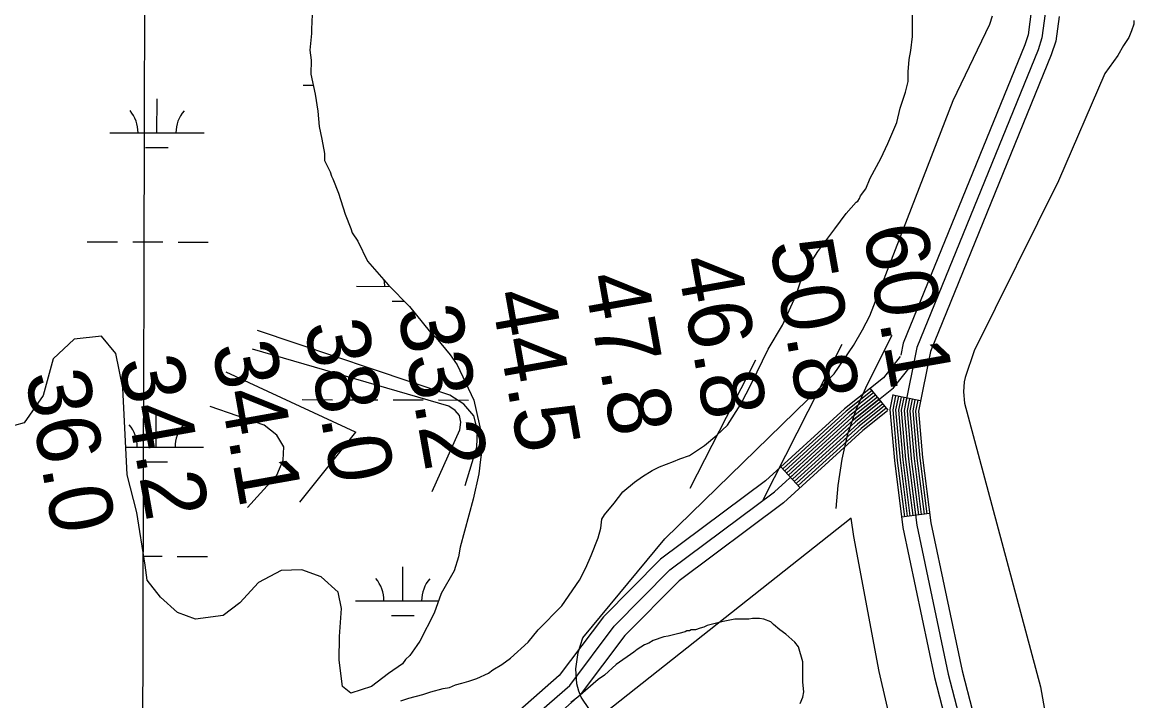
# Model space of a CAD drawing. Extents: x 3161665 to 3199565, y 885729 to 911164.
# Drawn here: x 3181436 to 3182612, y 894901 to 895619 of the extents above; entities that cross this region are included whole.
import ezdxf

# ---------------------------------------------------------------- set-up
doc = ezdxf.new("R2010")
doc.units = 0
for name, color, linetype in [('V-GRID-MAJR', 7, 'Continuous'), ('V-LEVE-TOET', 7, 'Continuous'), ('V-RIVR-RANG', 7, 'Continuous'), ('V-ROAD-CNTR', 7, 'Continuous'), ('V-SITE-VEGE', 7, 'Continuous'), ('V-TOPO-MAJR', 7, 'Continuous'), ('V-TOPO-MINR', 7, 'Continuous'), ('V-WETL-SWMP', 7, 'Continuous')]:
    doc.layers.add(name, color=color, linetype=linetype)

msp = doc.modelspace()

# ---------------------------------------------------------------- linework, layer by layer
at = {"layer": 'V-GRID-MAJR'}
msp.add_spline([(3181553.2, 891152.2), (3181570, 897211.5), (3181586.7, 903274.3), (3181603.5, 909337.1), (3181603.5, 909340.5)], degree=3, dxfattribs=at)
at = {"layer": 'V-LEVE-TOET'}
for points in [[(3182036.4, 894891.6), (3182027.8, 894904.4), (3182025, 894911), (3182023, 894918.6), (3182022.1, 894934.6), (3182024.5, 894951.6), (3182029.4, 894967.4), (3182116.1, 895071.9), (3182295.5, 895246.7), (3182315.8, 895276.7), (3182325.3, 895293.3), (3182333.3, 895308), (3182421.3, 895535.9), (3182460.1, 895616.9), (3182462.8, 895625.4)], [(3182612.4, 895620.5), (3182612.4, 895616.7), (3182610.1, 895609.5), (3182607.1, 895602.7), (3182601.6, 895594.3), (3182595.6, 895583.6), (3182581.8, 895564.4), (3182532.7, 895451.1), (3182443.5, 895271.1), (3182433.9, 895242.9), (3182433.1, 895238.3), (3182432.2, 895227.5), (3182433.2, 895215.6), (3182513.7, 894915.5), (3182565.9, 894618.7)], [(3182392.9, 894716.8), (3182343.1, 894931.5), (3182316.2, 895074.4), (3182313.5, 895094), (3182053.3, 894888.4)]]:
    msp.add_lwpolyline(points, dxfattribs=at)
at = {"layer": 'V-ROAD-CNTR'}
for p, q in [((3182352.4, 895208.1), (3182333.6, 895231.5)), ((3182386.8, 895218.1), (3182357.4, 895224.1)), ((3182259.3, 895126.2), (3182239.1, 895148.4)), ((3182396.4, 895098.9), (3182366.7, 895095.1))]:
    msp.add_line(p, q, dxfattribs=at)
for points in [[(3182186, 897012.1), (3182128.5, 896707.1), (3182101.9, 896553.8), (3182092.4, 896498.4), (3182091.5, 896433.3), (3182116.3, 896348.5), (3182137.8, 896319.4), (3182301.4, 896052), (3182392.7, 895899.5), (3182447.6, 895808.6), (3182483.2, 895746), (3182489.6, 895725.4), (3182502.9, 895675.6), (3182505.8, 895644.3), (3182500.6, 895605.6), (3182497, 895594.9), (3182368.5, 895279), (3182366.1, 895266.6)], [(3182520.9, 895644), (3182515.3, 895602.1), (3182511.1, 895589.7), (3182383, 895274.7), (3182369.4, 895208), (3182374, 895156.4), (3182382.9, 895086.5), (3182416.2, 894928.7), (3182470.9, 894717.4)], [(3182533.4, 895624.9), (3182530, 895598.7), (3182525.1, 895584.4), (3182397.4, 895270.3), (3182384.6, 895207.1), (3182388.9, 895158), (3182397.7, 895089), (3182430.8, 894932.2), (3182485.5, 894720.8)], [(3182365.4, 895265.2), (3182347.5, 895242.6), (3182306.2, 895209.5), (3182222.7, 895133.4), (3182111.7, 895050.4), (3182051.1, 894989.5), (3182004.4, 894927.3), (3181947.9, 894877.6), (3181907, 894855.9), (3181840.5, 894847.8), (3181780.8, 894854.2), (3181703.8, 894842.1), (3181580.2, 894803.2), (3181488.8, 894772.4), (3181360.2, 894715.8), (3181245.5, 894652.3), (3181099.7, 894575.8), (3180964.1, 894510.3)], [(3181366.8, 894702.4), (3181494.3, 894758.4), (3181584.8, 894788.9), (3181707.2, 894827.4), (3181781.2, 894839), (3181840.6, 894832.7), (3181911.6, 894841.4), (3181956.5, 894865.2), (3182015.5, 894917), (3182062.5, 894979.6), (3182121.6, 895039.1), (3182232.2, 895121.9), (3182316, 895198.1), (3182358.2, 895232), (3182377.2, 895255.9)], [(3182335.5, 895229.1), (3182308.2, 895207.2), (3182241.1, 895146.2)], [(3182357.5, 895224.7), (3182354.3, 895208.8), (3182359.1, 895154.8), (3182368.1, 895084), (3182401.6, 894925.3), (3182456.3, 894713.9), (3182481.4, 894597.4), (3182490.3, 894538.3), (3182490.2, 894502.8), (3182466.9, 894475.2), (3182452.5, 894467.5), (3182405, 894454.4), (3182202.3, 894432.3), (3182163.1, 894419), (3182124.8, 894399.2), (3182097, 894380.7), (3182070.1, 894351.7), (3182049.1, 894300.2), (3182042.8, 894254), (3182048.3, 894102.2), (3182076, 893799.8), (3182076.4, 893721.6)], [(3182337.4, 895226.8), (3182310.1, 895204.9), (3182243.1, 895143.9)], [(3182339.3, 895224.4), (3182312.1, 895202.6), (3182245.1, 895141.7)], [(3182341.1, 895222.1), (3182314, 895200.4), (3182247.1, 895139.5)], [(3182343, 895219.8), (3182316, 895198.1), (3182249.2, 895137.3)], [(3182344.9, 895217.4), (3182317.9, 895195.8), (3182251.2, 895135.1)], [(3182360.3, 895223.5), (3182357.3, 895208.7), (3182362.1, 895155.1), (3182369.7, 895095.5)], [(3182363.3, 895222.9), (3182360.4, 895208.5), (3182365.1, 895155.4), (3182372.6, 895095.9)], [(3182366.2, 895222.3), (3182363.4, 895208.3), (3182368, 895155.7), (3182375.6, 895096.3)], [(3182369.2, 895221.7), (3182366.4, 895208.2), (3182371, 895156), (3182378.6, 895096.6)], [(3182372.1, 895221.1), (3182369.4, 895208), (3182374, 895156.4), (3182381.6, 895097)], [(3182375, 895220.5), (3182372.5, 895207.8), (3182377, 895156.7), (3182384.5, 895097.4)], [(3182378, 895219.9), (3182375.5, 895207.6), (3182380, 895157), (3182387.5, 895097.8)], [(3182380.9, 895219.3), (3182378.5, 895207.5), (3182383, 895157.3), (3182390.5, 895098.2)], [(3182383.9, 895218.7), (3182381.5, 895207.3), (3182385.9, 895157.6), (3182393.5, 895098.5)], [(3182351.7, 895207.5), (3182325.7, 895186.7), (3182241.8, 895110.3), (3182131.5, 895027.7), (3182073.8, 894969.8), (3182026.6, 894906.8), (3181965.1, 894852.8), (3181916.2, 894826.8), (3181840.7, 894817.6), (3181781.6, 894823.9), (3181710.6, 894812.8), (3181589.5, 894774.7), (3181499.7, 894744.4), (3181373.5, 894688.9)], [(3182346.8, 895215.1), (3182319.9, 895193.5), (3182253.2, 895132.8)], [(3182348.7, 895212.8), (3182321.8, 895191.2), (3182255.2, 895130.6)], [(3182350.5, 895210.4), (3182323.8, 895189), (3182257.2, 895128.4)]]:
    msp.add_lwpolyline(points, dxfattribs=at)
at = {"layer": 'V-SITE-VEGE'}
for p, q in [((3182378.4, 895603.8), (3182378.4, 895634.7)), ((3182376.6, 895588.8), (3182378.4, 895603.8)), ((3182374.7, 895579.4), (3182376.6, 895588.8)), ((3182373.8, 895566.3), (3182374.7, 895579.4)), ((3182373.8, 895556), (3182373.8, 895566.3)), ((3182370.9, 895544.7), (3182373.8, 895556)), ((3182365.3, 895527.8), (3182370.9, 895544.7)), ((3182361.6, 895512.8), (3182365.3, 895527.8)), ((3182352.2, 895490.3), (3182361.6, 895512.8)), ((3182344.7, 895474.4), (3182352.2, 895490.3)), ((3182333.5, 895453.8), (3182344.7, 895474.4)), ((3182328.8, 895442.5), (3182333.5, 895453.8)), ((3182323.1, 895435), (3182328.8, 895442.5)), ((3182318.5, 895428.5), (3182320.3, 895429.4)), ((3182320.3, 895429.4), (3182322.2, 895432.2)), ((3182322.2, 895432.2), (3182323.1, 895435)), ((3182308.1, 895416.3), (3182318.5, 895428.5)), ((3182296, 895400.3), (3182308.1, 895416.3)), ((3182278.2, 895376), (3182296, 895400.3)), ((3182269.7, 895362.8), (3182278.2, 895376)), ((3182260.3, 895346), (3182269.7, 895362.8)), ((3182254.7, 895329.1), (3182260.3, 895346)), ((3182240.7, 895298.2), (3182254.7, 895329.1)), ((3182225.7, 895272.9), (3182240.7, 895298.2)), ((3182207.9, 895236.3), (3182225.7, 895272.9)), ((3182196.6, 895214.7), (3182207.9, 895236.3)), ((3182182.6, 895192.2), (3182196.6, 895214.7)), ((3182158.2, 895170.7), (3182171.3, 895181.9)), ((3182171.3, 895181.9), (3182182.6, 895192.2)), ((3182150.7, 895166), (3182158.2, 895170.7)), ((3182131.9, 895156.6), (3182142.2, 895160.4)), ((3182142.2, 895160.4), (3182150.7, 895166)), ((3182102.9, 895144.4), (3182110.4, 895148.2)), ((3182110.4, 895148.2), (3182125.4, 895153.8)), ((3182125.4, 895153.8), (3182131.9, 895156.6)), ((3182084.1, 895132.2), (3182092.6, 895137.9)), ((3182092.6, 895137.9), (3182102.9, 895144.4)), ((3182071.9, 895121.9), (3182084.1, 895132.2)), ((3182062.6, 895109.7), (3182071.9, 895121.9)), ((3182052.3, 895097.6), (3182062.6, 895109.7)), ((3182048.5, 895083.5), (3182049.5, 895092.9)), ((3182049.5, 895092.9), (3182052.3, 895097.6)), ((3182045.7, 895073.2), (3182048.5, 895083.5)), ((3182038.2, 895054.4), (3182045.7, 895073.2)), ((3182032.6, 895041.3), (3182038.2, 895054.4)), ((3182026, 895028.2), (3182032.6, 895041.3)), ((3182007.3, 895001), (3182026, 895028.2)), ((3181982, 894975.7), (3182007.3, 895001)), ((3182169.4, 894982.3), (3182161, 894980.4)), ((3182176, 894984.1), (3182169.4, 894982.3)), ((3182190.1, 894987), (3182176, 894984.1)), ((3182205.1, 894987), (3182190.1, 894987)), ((3182208.8, 894987.9), (3182205.1, 894987)), ((3182216.3, 894987.9), (3182208.8, 894987.9)), ((3182221, 894987), (3182216.3, 894987.9)), ((3182228.5, 894984.1), (3182221, 894987)), ((3182231.3, 894981.3), (3182228.5, 894984.1)), ((3181971.7, 894962.6), (3181982, 894975.7)), ((3182131, 894972), (3182119.8, 894969.1)), ((3182137.6, 894973.8), (3182131, 894972)), ((3182139.5, 894974.8), (3182137.6, 894973.8)), ((3182142.3, 894974.8), (3182139.5, 894974.8)), ((3182144.1, 894975.7), (3182142.3, 894974.8)), ((3182148.8, 894975.7), (3182144.1, 894975.7)), ((3182153.5, 894977.6), (3182148.8, 894975.7)), ((3182157.3, 894978.5), (3182153.5, 894977.6)), ((3182161, 894980.4), (3182157.3, 894978.5)), ((3182237.9, 894975.7), (3182231.3, 894981.3)), ((3182244.4, 894971), (3182237.9, 894975.7)), ((3182253.8, 894962.6), (3182244.4, 894971)), ((3181952.9, 894945.7), (3181971.7, 894962.6)), ((3182094.5, 894959.8), (3182087, 894955.1)), ((3182099.1, 894961.6), (3182094.5, 894959.8)), ((3182103.8, 894964.5), (3182099.1, 894961.6)), ((3182115.1, 894968.2), (3182103.8, 894964.5)), ((3182119.8, 894969.1), (3182115.1, 894968.2)), ((3182257.6, 894957.9), (3182253.8, 894962.6)), ((3182083.2, 894952.3), (3182064.5, 894939.1)), ((3182087, 894955.1), (3182083.2, 894952.3)), ((3182262.2, 894942), (3182257.6, 894957.9)), ((3181934.2, 894933.5), (3181943.5, 894939.1)), ((3181943.5, 894939.1), (3181952.9, 894945.7)), ((3182064.5, 894939.1), (3182052.3, 894927.9)), ((3182262.2, 894920.4), (3182262.2, 894942)), ((3181908.9, 894921.3), (3181917.3, 894924.1)), ((3181917.3, 894924.1), (3181929.5, 894929.8)), ((3181929.5, 894929.8), (3181934.2, 894933.5)), ((3182045.7, 894923.2), (3182024.2, 894904.5)), ((3182052.3, 894927.9), (3182045.7, 894923.2)), ((3181868.6, 894910.1), (3181881.7, 894913.8)), ((3181881.7, 894913.8), (3181888.2, 894914.8)), ((3181888.2, 894914.8), (3181894.8, 894917.6)), ((3181894.8, 894917.6), (3181901.4, 894919.4)), ((3181901.4, 894919.4), (3181908.9, 894921.3)), ((3182263.2, 894910.1), (3182262.2, 894920.4)), ((3181836.7, 894900.7), (3181845.1, 894903.5)), ((3181845.1, 894903.5), (3181860.1, 894907.3)), ((3181860.1, 894907.3), (3181868.6, 894910.1)), ((3182024.2, 894904.5), (3182016.7, 894898.8)), ((3182259.4, 894897.9), (3182262.2, 894904.5)), ((3182262.2, 894904.5), (3182263.2, 894910.1))]:
    msp.add_line(p, q, dxfattribs=at)
at = {"layer": 'V-TOPO-MAJR'}
for points in [[(3181870.1, 895122.3), (3181899.1, 895187.3), (3181900.2, 895195.5), (3181899, 895202.5), (3181894.4, 895208), (3181887.5, 895212.4), (3181679.9, 895272.7)], [(3181651.5, 895248.7), (3181788.6, 895185.3), (3181788.7, 895185.2), (3181788.8, 895185.1), (3181788.7, 895184.8), (3181729.5, 895110.7)], [(3181674.4, 895105.2), (3181705.6, 895139.5), (3181712.2, 895155.2), (3181713.1, 895169.5), (3181705.4, 895181.7), (3181692.1, 895192.3), (3181635.1, 895212.2)]]:
    msp.add_lwpolyline(points, dxfattribs=at)
at = {"layer": 'V-TOPO-MINR'}
for points in [[(3181905, 895128.6), (3181917.1, 895169.1), (3181917.8, 895186.9), (3181914, 895202.4), (3181903.5, 895214.5), (3181888.6, 895224.2), (3181685.2, 895292.6)], [(3182297.5, 895104.3), (3182299.6, 895128.6), (3182303.7, 895156.2), (3182309.8, 895183.3), (3182319, 895209.6), (3182330.2, 895235.2), (3182356.7, 895287.5)], [(3182220.4, 895113.5), (3182303.8, 895278)], [(3182143, 895125.8), (3182212.5, 895261.5)]]:
    msp.add_lwpolyline(points, dxfattribs=at)
at = {"layer": 'V-WETL-SWMP'}
for p, q in [((3181733.5, 895552), (3181744.2, 895552)), ((3181578.7, 895501.7), (3181578.8, 895537.7)), ((3181528.7, 895501.9), (3181628.7, 895501.6)), ((3181566.7, 895486.3), (3181590.7, 895486.2)), ((3181505, 895386.5), (3181537, 895386.4)), ((3181553, 895386.4), (3181585, 895386.3)), ((3181601, 895386.2), (3181633, 895386.1)), ((3181789.7, 895339.3), (3181825, 895339.2)), ((3181827.7, 895323.7), (3181840.2, 895323.7)), ((3181732.5, 895219.4), (3181764.5, 895219.3)), ((3181780.5, 895219.2), (3181812.5, 895219.1)), ((3181828.5, 895219.1), (3181860.5, 895219)), ((3181876.5, 895219), (3181908.5, 895218.9)), ((3181577.8, 895169), (3181577.9, 895205)), ((3181545.9, 895169.1), (3181627.8, 895168.9)), ((3181565.8, 895153.6), (3181589.8, 895153.6)), ((3181564.7, 895053.6), (3181584.1, 895053.6)), ((3181600.1, 895053.5), (3181632.1, 895053.5)), ((3181838.8, 895006.5), (3181838.9, 895042.5)), ((3181788.8, 895006.6), (3181876.7, 895006.4)), ((3181826.8, 894991.1), (3181850.8, 894991))]:
    msp.add_line(p, q, dxfattribs=at)
for points in [[(3181743.8, 895642.9), (3181742.1, 895611.5), (3181742.1, 895607), (3181740.4, 895589.1), (3181741.9, 895578.6), (3181741.7, 895563.7), (3181746.1, 895542.8), (3181748.9, 895524.8), (3181750.3, 895508.3), (3181753.2, 895494.9), (3181756.1, 895479.9), (3181756, 895472.4), (3181761.9, 895460.4), (3181763.4, 895455.9), (3181764.8, 895452.9), (3181770.7, 895438), (3181778, 895415.5), (3181783.9, 895400.5), (3181785.3, 895396), (3181791.2, 895387), (3181801.5, 895366), (3181823.8, 895340.4), (3181846, 895317.9), (3181866.7, 895292.3), (3181874.1, 895284.8), (3181889, 895266.7), (3181896.3, 895256.2), (3181914, 895218.7), (3181922.7, 895179.8), (3181922.6, 895166.3), (3181921, 895155.9), (3181919.4, 895141), (3181913.2, 895114.1), (3181899.4, 895063.4), (3181897.8, 895053), (3181893.2, 895038.1), (3181879.6, 895014.2), (3181872, 894993.4), (3181856.8, 894963.6), (3181853.8, 894959.1), (3181846.2, 894948.7), (3181841.7, 894944.3), (3181838.7, 894939.8), (3181823.7, 894929.5), (3181805.8, 894915.9), (3181783.9, 894908.8), (3181775.2, 894915.8), (3181771.5, 894943.7)], [(3181771.5, 894943.7), (3181771.7, 894968.6), (3181773.9, 894998.4), (3181770.6, 895015.6), (3181752.3, 895031.8), (3181732.1, 895039.3), (3181710.3, 895038.6), (3181686.1, 895025.8), (3181666.4, 895004.2), (3181648.7, 894990.9), (3181619.6, 894986.9), (3181600.6, 894994), (3181582.3, 895010.2), (3181568.3, 895028.2), (3181566.1, 895044.3), (3181557.4, 895099.8), (3181547.3, 895139.7), (3181542.7, 895231.9), (3181535.3, 895268.3), (3181520.1, 895286.4), (3181491, 895283.2), (3181468.7, 895262.7), (3181458.1, 895223.7), (3181438, 895194.8), (3181417.7, 895189.2)]]:
    msp.add_lwpolyline(points, dxfattribs=at)
for centre, start, end in [((3181523.5, 895502.3), 359.0698, 40.6135), ((3181634, 895502), 139.0698, 180.6135), ((3181784.5, 895339.8), 359.0698, 9.6027), ((3181522.6, 895169.7), 359.0698, 40.6135), ((3181633.1, 895169.4), 139.0698, 180.6135), ((3181783.6, 895007.1), 359.0698, 40.6135), ((3181894, 895006.8), 139.0698, 180.6135)]:
    msp.add_arc(centre, 35.2, start, end, dxfattribs=at)

# ---------------------------------------------------------------- texts
at = {"layer": 'V-RIVR-RANG'}
for s, p in [('60.1', (3182325.7, 895400.2)), ('50.8', (3182226.9, 895384.8)), ('46.8', (3182128.5, 895367.1)), ('47.8', (3182030.1, 895349.3)), ('44.5', (3181931.7, 895331.6)), ('33.2', (3181833.2, 895313.8)), ('38.0', (3181734.3, 895298.9)), ('34.1', (3181636.8, 895276)), ('34.2', (3181538, 895260.6)), ('36.0', (3181439.1, 895245.7))]:
    msp.add_text(s, height=67, rotation=280.0783, dxfattribs=at).set_placement(p)

doc.saveas('drawing.dxf')
